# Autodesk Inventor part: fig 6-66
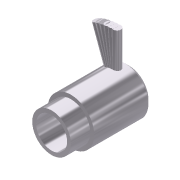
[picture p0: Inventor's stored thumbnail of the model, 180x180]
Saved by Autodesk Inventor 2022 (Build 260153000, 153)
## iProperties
Created: 2001-12
Part Number: fig 6-66
Document SubType Name: Modeling
Designer: Renu Muthoo
Density: 1 g/cm^3
Material: Generic
Appearance: Metal-AL-6061 (Polished)
Control State: 0
Master: False
Checked Out: False
Shininess: 77.0
Angle Display Precision: 2
Document Length Units: 11269
Document Angle Units: 11279
Document Time Units: 11290
Document Mass Units: 11283
Document Length Units Precision: 3
Document Angle Units Precision: 2
Compacted: True
Density: 0.0
Volumn: 0.0
Area: 0.0
PropertySet Name: Model Information
Author: Renu Muthoo
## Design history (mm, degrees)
sketch "Sketch2"
  geometry: L1 (-9.573, -4.327)-(-9.573, -5.327); L2 (-9.573, -5.327)-(-4.573, -5.327); L3 (-4.573, -5.327)-(-4.573, -6.327); L4 (-4.573, -6.327)-(9.427, -6.327); L5 (9.427, -6.327)-(10.427, -5.327); L6 (10.427, -5.327)-(10.427, -4.327); L7 (10.427, -4.327)-(-9.573, -4.327); L8 (-13.687, -0.327)-(14, -0.327)
  constraints: 16 end point, 5 parallel, 1 perpendicular, 1 vertical
  dimensions: "d9" = 20 distance of L6.end L1.start; "d10" = 5 distance of L1.end L2.end; "d11" = 12 diameter of L4 L8; "d12" = 10 diameter of L2 L8; "d13" = 8 diameter of L7 L8; "d14" = 45 deg angle of L5 L4; "d15" = 1 horizontal distance of L5.end L4.end
revolve "Revolution2" sketch "Sketch2" stored, may be unused: angle "d16" = 90 deg
workplane "Work Plane1"
workplane "Work Plane2"
sketch "Sketch3"
  geometry: L1 (-4, 8)-(4, 8) reference; C1 r 1 at (-0.098, 5)
  constraints: 1 centre point
  dimensions: "d18" = 3 distance from line of L1 C1.centre; "d19" = 2 diameter of C1
extrude "Extrusion1" join sketch "Sketch3" distance "d20" = 10; taper "d21" = 0 deg
pattern_circular "Circular Pattern3" dims angle "d29" = 20 deg
body "Solid1"
other parameters: "d17" = -1
